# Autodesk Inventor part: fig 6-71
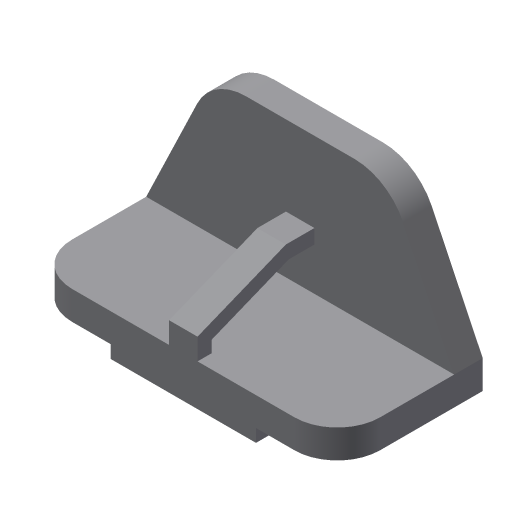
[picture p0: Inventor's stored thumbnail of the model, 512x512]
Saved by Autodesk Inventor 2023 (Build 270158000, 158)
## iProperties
Created: 2001-12
Part Number: fig 6-71
Document SubType Name: Modeling
Designer: Renu Muthoo
Density: 1 g/cm^3
Material: Generic
Appearance: Default
Control State: 0
Master: False
Checked Out: False
Shininess: 77.0
Length Units: 11269
Angle Units: 11279
Time Units: 11290
Mass Units: 11283
Length Display Precision: 3
Angle Display Precision: 2
Density: 0.0
Volumn: 0.0
Area: 0.0
PropertySet Name: Model Information
Author: Renu Muthoo
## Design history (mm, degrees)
sketch "Sketch2"
  geometry: L1 (-67.219, 19.116)-(148.781, 19.116); L2 (148.781, 19.116)-(148.781, -0.884); L3 (-67.219, -0.884)-(-67.219, 19.116); L4 (-10.219, -0.884)-(-10.219, -9.884); L5 (-10.219, -9.884)-(91.781, -9.884); L6 (91.781, -9.884)-(91.781, -0.884); L7 (148.781, -0.884)-(91.781, -0.884); L8 (-10.219, -0.884)-(-67.219, -0.884)
  constraints: 16 end point, 5 parallel, 4 perpendicular, 2 equal length, 1 horizontal
  dimensions: "d0" = 102 distance of L4.end L5.end; "d1" = 57 distance of L4.start L3.start; "d2" = 29 distance between parallel lines of L1 L5; "d3" = 20 distance of L1.end L2.end
extrude "Extrusion1" new body sketch "Sketch2" distance "d4" = 102; taper "d5" = 0 deg
sketch "Sketch3"
  geometry: L1 (67.219, -19.116)-(-148.781, -19.116) reference; L2 (67.219, -19.116)-(31.475, -93.564); L3 (-2.781, -115.116)-(-78.781, -115.116); L4 (-113.038, -93.564)-(-148.781, -19.116); A1 r 38 centre (-2.781, -77.116) between (-2.781, -115.116) and (31.475, -93.564); A2 r 38 centre (-78.781, -77.116) between (-113.038, -93.564) and (-78.781, -115.116)
  constraints: 6 end point, 4 point on circle, 4 tangent, 2 centre point, 1 equal length, 1 equal radius, 1 parallel
  dimensions: "d6" = 96 distance between parallel lines of L3 L1; "d7" = 38 radius of A1; "d8" = 76 distance of A2.centre A1.centre
extrude "Extrusion2" join sketch "Sketch3" distance "d9" = 20; taper "d10" = 0 deg
fillet "Fillet1" dims "d11" = 30
workplane "Work Plane1"
sketch "Sketch7"
  geometry: L1 (0, -82)-(-15, -82); L2 (-15, -82)-(-40, -20); L3 (-40, -20)-(-40, 0); L4 (0, -82)-(20, -82) reference; L5 (0, 0)-(-74.447, 0) reference
  constraints: 6 end point, 2 point on line, 1 horizontal, 1 perpendicular
  dimensions: "d32" = 20 distance of L2.end L3.end; "d33" = 15 distance of L1.start L1.end; "d34" = 40 distance of L5.start L3.end
feature "Rib4" sketch "Sketch7" dims "d55" = 10, "d56" = 20, "d57" = 0
body "Solid1"
other parameters: "d12" = -108
